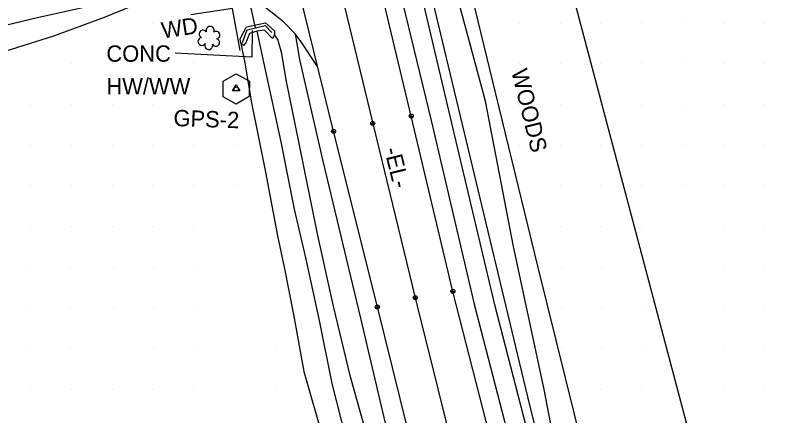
# Model space of a CAD drawing. Extents: x 1548934 to 1561348, y 809680 to 824075.
# Drawn here: x 1551496.2 to 1551685.3, y 811503.6 to 811602 of the extents above; entities that cross this region are included whole.
import ezdxf

# ---------------------------------------------------------------- set-up
doc = ezdxf.new("R2010")
doc.units = 0
for name, color, linetype in [('_CIVIL_CONSTRUCTION', 7, 'Continuous'), ('Default', 7, 'Continuous'), ('E_NCDOT_Horizontal_Alignment', 7, 'Continuous'), ('E_NCDOT_Vertical_Profile_Ground_Line', 7, 'Continuous'), ('Exist DTM QL2 LIDAR Elevation Point', 7, 'Continuous'), ('Exist Other Culture Fence Line Text', 7, 'Continuous'), ('Exist Structure Minor Culvert Topo', 7, 'Continuous'), ('Exist Structure Minor Head and End Wall Leader', 7, 'Continuous'), ('Exist Structure Minor Head and End Wall Text', 7, 'Continuous'), ('Exist Vegetation Shrub CELL', 7, 'Continuous'), ('Exist Vegetation Woods Line', 7, 'Continuous'), ('Exist Vegetation Woods Line Text', 7, 'Continuous'), ('P_NCDOT_Horizontal_Alignment', 7, 'Continuous'), ('P_NCDOT_Vertical_Profile_Grade_Minor_Road', 7, 'Continuous'), ('P_RDY_Dimension_Text', 7, 'Continuous'), ('P_RDY_Guardrail_Attenuator_Cell', 7, 'Continuous'), ('P_RDY_Paved_Shoulder', 7, 'Continuous'), ('PH Exist DTM Breakline', 7, 'Continuous'), ('Scratch_Level_6', 7, 'Continuous')]:
    doc.layers.add(name, color=color, linetype=linetype)

# ---------------------------------------------------------------- blocks, each defined once
blk = doc.blocks.new('SurveyPointCell')
at = {"layer": 'Default'}
for p, q in [((-0.5, 0), (0.5, 0)), ((0, -0.5), (0, 0.5))]:
    blk.add_line(p, q, dxfattribs=at)
blk.add_circle((0, 0), 0.5, dxfattribs=at)

msp = doc.modelspace()

# ---------------------------------------------------------------- linework, layer by layer
at = {"layer": '_CIVIL_CONSTRUCTION'}
msp.add_line((1551550.43, 811583.92), (1551550.43, 811583.92), dxfattribs=at)
msp.add_line((1551550.43, 811583.92), (1551550.43, 811583.92), dxfattribs=at)
msp.add_line((1551550.43, 811583.92), (1551550.43, 811583.92), dxfattribs=at)
msp.add_lwpolyline([(1551547.2, 811585.79), (1551550.45, 811587.6), (1551553.7, 811585.81), (1551553.65, 811582.09), (1551550.4, 811580.2), (1551547.2, 811582.01)], close=True, dxfattribs=at)
msp.add_lwpolyline([(1551547.2, 811585.79), (1551550.45, 811587.6), (1551553.7, 811585.81), (1551553.65, 811582.09), (1551550.4, 811580.2), (1551547.2, 811582.01)], close=True, dxfattribs=at)
msp.add_lwpolyline([(1551547.2, 811585.79), (1551550.45, 811587.6), (1551553.7, 811585.81), (1551553.65, 811582.09), (1551550.4, 811580.2), (1551547.2, 811582.01)], close=True, dxfattribs=at)
at = {"layer": 'E_NCDOT_Vertical_Profile_Ground_Line'}
for points in [[(1551637.28, 811403.02), (1551626.4, 811444.66), (1551615.07, 811489.43), (1551603.65, 811534.15), (1551593.42, 811577.24), (1551582.77, 811621.83), (1551571.37, 811669.46), (1551560.56, 811714.33), (1551550.2, 811757.15), (1551539.19, 811800.15), (1551527.36, 811844.37)], [(1551618.39, 811397.72), (1551607.45, 811440.85), (1551596.26, 811485.28), (1551585.1, 811530.33), (1551574.36, 811573.51), (1551563.53, 811617.58), (1551552.6, 811664.91), (1551541.75, 811709.22), (1551531.12, 811752.56), (1551520.63, 811794.97), (1551508.88, 811839.17)]]:
    msp.add_lwpolyline(points, dxfattribs=at)
at = {"layer": 'Exist DTM QL2 LIDAR Elevation Point'}
for p, q in [((1551529.98, 811600.06), (1551529.98, 811600.06)), ((1551539.98, 811600.06), (1551539.98, 811600.06)), ((1551619.99, 811600.06), (1551619.99, 811600.06)), ((1551629.99, 811600.06), (1551629.99, 811600.06)), ((1551639.99, 811600.06), (1551639.99, 811600.06)), ((1551649.99, 811600.06), (1551649.99, 811600.06)), ((1551659.99, 811600.06), (1551659.99, 811600.06)), ((1551669.99, 811600.06), (1551669.99, 811600.06)), ((1551679.99, 811600.06), (1551679.99, 811600.06)), ((1551509.98, 811590.06), (1551509.98, 811590.06)), ((1551519.98, 811590.06), (1551519.98, 811590.06)), ((1551529.98, 811590.06), (1551529.98, 811590.06)), ((1551539.98, 811590.06), (1551539.98, 811590.06)), ((1551619.99, 811590.06), (1551619.99, 811590.06)), ((1551629.99, 811590.06), (1551629.99, 811590.06)), ((1551639.99, 811590.06), (1551639.99, 811590.06)), ((1551649.99, 811590.06), (1551649.99, 811590.06)), ((1551659.99, 811590.06), (1551659.99, 811590.06)), ((1551669.99, 811590.06), (1551669.99, 811590.06)), ((1551679.99, 811590.06), (1551679.99, 811590.06)), ((1551499.98, 811580.06), (1551499.98, 811580.06)), ((1551509.98, 811580.06), (1551509.98, 811580.06)), ((1551519.98, 811580.06), (1551519.98, 811580.06)), ((1551529.98, 811580.06), (1551529.98, 811580.06)), ((1551539.98, 811580.06), (1551539.98, 811580.06)), ((1551619.99, 811580.06), (1551619.99, 811580.06)), ((1551629.99, 811580.06), (1551629.99, 811580.06)), ((1551639.99, 811580.06), (1551639.99, 811580.06)), ((1551649.99, 811580.06), (1551649.99, 811580.06)), ((1551659.99, 811580.06), (1551659.99, 811580.06)), ((1551669.99, 811580.06), (1551669.99, 811580.06)), ((1551679.99, 811580.06), (1551679.99, 811580.06)), ((1551499.98, 811570.06), (1551499.98, 811570.06)), ((1551509.98, 811570.06), (1551509.98, 811570.06)), ((1551519.98, 811570.06), (1551519.98, 811570.06)), ((1551529.98, 811570.06), (1551529.98, 811570.06)), ((1551539.98, 811570.06), (1551539.98, 811570.06)), ((1551549.98, 811570.06), (1551549.98, 811570.06)), ((1551619.99, 811570.06), (1551619.99, 811570.06)), ((1551629.99, 811570.06), (1551629.99, 811570.06)), ((1551639.99, 811570.06), (1551639.99, 811570.06)), ((1551649.99, 811570.06), (1551649.99, 811570.06)), ((1551659.99, 811570.06), (1551659.99, 811570.06)), ((1551669.99, 811570.06), (1551669.99, 811570.06)), ((1551679.99, 811570.06), (1551679.99, 811570.06)), ((1551499.98, 811560.06), (1551499.98, 811560.06)), ((1551509.98, 811560.06), (1551509.98, 811560.06)), ((1551519.98, 811560.06), (1551519.98, 811560.06)), ((1551529.98, 811560.06), (1551529.98, 811560.06)), ((1551539.98, 811560.06), (1551539.98, 811560.06)), ((1551549.98, 811560.06), (1551549.98, 811560.06)), ((1551629.99, 811560.06), (1551629.99, 811560.06)), ((1551639.99, 811560.06), (1551639.99, 811560.06)), ((1551649.99, 811560.06), (1551649.99, 811560.06)), ((1551659.99, 811560.06), (1551659.99, 811560.06)), ((1551669.99, 811560.06), (1551669.99, 811560.06)), ((1551679.99, 811560.06), (1551679.99, 811560.06)), ((1551499.98, 811550.05), (1551499.98, 811550.05)), ((1551509.98, 811550.05), (1551509.98, 811550.05)), ((1551519.98, 811550.05), (1551519.98, 811550.05)), ((1551529.98, 811550.05), (1551529.98, 811550.05)), ((1551539.98, 811550.05), (1551539.98, 811550.05)), ((1551549.98, 811550.05), (1551549.98, 811550.05)), ((1551629.99, 811550.05), (1551629.99, 811550.05)), ((1551639.99, 811550.05), (1551639.99, 811550.05)), ((1551649.99, 811550.05), (1551649.99, 811550.05)), ((1551659.99, 811550.05), (1551659.99, 811550.05)), ((1551669.99, 811550.05), (1551669.99, 811550.05)), ((1551679.99, 811550.05), (1551679.99, 811550.05)), ((1551499.98, 811540.05), (1551499.98, 811540.05)), ((1551509.98, 811540.05), (1551509.98, 811540.05)), ((1551519.98, 811540.05), (1551519.98, 811540.05)), ((1551529.98, 811540.05), (1551529.98, 811540.05)), ((1551539.98, 811540.05), (1551539.98, 811540.05)), ((1551549.98, 811540.05), (1551549.98, 811540.05)), ((1551629.99, 811540.05), (1551629.99, 811540.05)), ((1551639.99, 811540.05), (1551639.99, 811540.05)), ((1551649.99, 811540.05), (1551649.99, 811540.05)), ((1551659.99, 811540.05), (1551659.99, 811540.05)), ((1551669.99, 811540.05), (1551669.99, 811540.05)), ((1551679.99, 811540.05), (1551679.99, 811540.05)), ((1551499.98, 811530.05), (1551499.98, 811530.05)), ((1551509.98, 811530.05), (1551509.98, 811530.05)), ((1551519.98, 811530.05), (1551519.98, 811530.05)), ((1551529.98, 811530.05), (1551529.98, 811530.05)), ((1551539.98, 811530.05), (1551539.98, 811530.05)), ((1551549.98, 811530.05), (1551549.98, 811530.05)), ((1551629.99, 811530.05), (1551629.99, 811530.05)), ((1551639.99, 811530.05), (1551639.99, 811530.05)), ((1551649.99, 811530.05), (1551649.99, 811530.05)), ((1551659.99, 811530.05), (1551659.99, 811530.05)), ((1551669.99, 811530.05), (1551669.99, 811530.05)), ((1551679.99, 811530.05), (1551679.99, 811530.05)), ((1551499.98, 811520.05), (1551499.98, 811520.05)), ((1551509.98, 811520.05), (1551509.98, 811520.05)), ((1551529.98, 811520.05), (1551529.98, 811520.05)), ((1551539.98, 811520.05), (1551539.98, 811520.05)), ((1551549.98, 811520.05), (1551549.98, 811520.05)), ((1551559.98, 811520.05), (1551559.98, 811520.05)), ((1551629.99, 811520.05), (1551629.99, 811520.05)), ((1551639.99, 811520.05), (1551639.99, 811520.05)), ((1551649.99, 811520.05), (1551649.99, 811520.05)), ((1551659.99, 811520.05), (1551659.99, 811520.05)), ((1551669.99, 811520.05), (1551669.99, 811520.05)), ((1551679.99, 811520.05), (1551679.99, 811520.05)), ((1551499.98, 811510.05), (1551499.98, 811510.05)), ((1551509.98, 811510.05), (1551509.98, 811510.05)), ((1551519.98, 811510.05), (1551519.98, 811510.05)), ((1551529.98, 811510.05), (1551529.98, 811510.05)), ((1551539.98, 811510.05), (1551539.98, 811510.05)), ((1551549.98, 811510.05), (1551549.98, 811510.05)), ((1551559.98, 811510.05), (1551559.98, 811510.05)), ((1551639.99, 811510.05), (1551639.99, 811510.05)), ((1551649.99, 811510.05), (1551649.99, 811510.05)), ((1551659.99, 811510.05), (1551659.99, 811510.05)), ((1551669.99, 811510.05), (1551669.99, 811510.05)), ((1551679.99, 811510.05), (1551679.99, 811510.05))]:
    msp.add_line(p, q, dxfattribs=at)
at = {"layer": 'Exist Structure Minor Culvert Topo'}
msp.add_line((1551555.22, 811598.91), (1551544.95, 811644.87), dxfattribs=at)
at = {"layer": 'Exist Structure Minor Head and End Wall Leader'}
msp.add_line((1551554.38, 811598.24), (1551554.25, 811591.73), dxfattribs=at)
at = {"layer": 'Exist Structure Minor Head and End Wall Text'}
msp.add_line((1551554.25, 811591.73), (1551535.46, 811592.71), dxfattribs=at)
at = {"layer": 'Exist Vegetation Shrub CELL'}
msp.add_line((1551543.8, 811596.27), (1551543.8, 811596.27), dxfattribs=at)
for centre, radius, start, end in [((1551544.03, 811598.31), 0.99, 334.8391, 200.4717), ((1551542.32, 811597.4), 0.968, 35.8908, 245.4216), ((1551545.48, 811597.14), 0.929, 284.4567, 126.0861), ((1551542, 811595.57), 0.955, 95.1099, 327.9534), ((1551543.68, 811594.59), 0.984, 151.2797, 21.387), ((1551545.44, 811595.34), 0.937, 204.9913, 73.4601)]:
    msp.add_arc(centre, radius, start, end, dxfattribs=at)
at = {"layer": 'Exist Vegetation Woods Line'}
msp.add_lwpolyline([(1551571.72, 811842.18), (1551613.6, 811680.5), (1551674.88, 811449.43), (1551691.44, 811358.19), (1551695.57, 811334.77), (1551700.55, 811312.09), (1551699.58, 811308.43), (1551693.58, 811303.93), (1551678.43, 811304.73), (1551672.72, 811312.99), (1551668.24, 811325.43), (1551622.53, 811506.2), (1551580.25, 811682.82), (1551545.51, 811843.36)], dxfattribs=at)
at = {"layer": 'P_NCDOT_Horizontal_Alignment'}
msp.add_line((1551550.43, 811583.92), (1551550.43, 811583.92), dxfattribs=at)
msp.add_line((1551550.43, 811583.92), (1551550.43, 811583.92), dxfattribs=at)
msp.add_line((1551550.43, 811583.92), (1551550.43, 811583.92), dxfattribs=at)
msp.add_lwpolyline([(1551549.57, 811583.42), (1551550.43, 811584.92), (1551551.3, 811583.42)], close=True, dxfattribs=at)
msp.add_lwpolyline([(1551549.57, 811583.42), (1551550.43, 811584.92), (1551551.3, 811583.42)], close=True, dxfattribs=at)
msp.add_lwpolyline([(1551549.57, 811583.42), (1551550.43, 811584.92), (1551551.3, 811583.42)], close=True, dxfattribs=at)
msp.add_circle((1551550.43, 811583.92), 0.5, dxfattribs=at)
msp.add_circle((1551550.43, 811583.92), 0.5, dxfattribs=at)
msp.add_circle((1551550.43, 811583.92), 0.5, dxfattribs=at)
at = {"layer": 'P_NCDOT_Vertical_Profile_Grade_Minor_Road'}
msp.add_lwpolyline([(1551518.46, 811841.68), (1551529.96, 811797.42), (1551540.4, 811755.31), (1551551.09, 811711.95), (1551562.08, 811668.09), (1551573.17, 811620.17), (1551583.96, 811575.43), (1551594.4, 811532.6), (1551605.57, 811487.55), (1551616.79, 811443.3), (1551627.43, 811400.69)], dxfattribs=at)
at = {"layer": 'P_RDY_Dimension_Text'}
for points in [[(1551587.8, 811693.01), (1551592.22, 811675.36), (1551603.34, 811627.3), (1551614.09, 811582.73), (1551624.5, 811540), (1551635.64, 811495.08), (1551646.85, 811450.87), (1551657.51, 811408.2)], [(1551551.39, 811593.34), (1551549.5, 811603.72), (1551539.28, 811602.16)]]:
    msp.add_lwpolyline(points, dxfattribs=at)
at = {"layer": 'P_RDY_Guardrail_Attenuator_Cell'}
msp.add_lwpolyline([(1551552.02, 811595.34), (1551553.17, 811598.4), (1551557.57, 811599.48), (1551559.15, 811597.81)], dxfattribs=at)
at = {"layer": 'P_RDY_Paved_Shoulder'}
for points in [[(1551519.39, 811605.3), (1551501.99, 811601.47), (1551487.86, 811598.11)], [(1551570.44, 811589.44), (1551566.2, 811595.74), (1551564.93, 811597.45), (1551562.14, 811600.35), (1551560.1, 811601.98), (1551555.9, 811605.25)]]:
    msp.add_lwpolyline(points, dxfattribs=at)
at = {"layer": 'PH Exist DTM Breakline'}
for points in [[(1551669.67, 811303.01), (1551663.46, 811331.84), (1551653.59, 811372.99), (1551648.84, 811392.4), (1551636.09, 811443.6), (1551626.8, 811481.01), (1551614.05, 811530.5), (1551603.71, 811574.11), (1551596.24, 811605.78), (1551582.53, 811665.38), (1551576.53, 811692.42), (1551569, 811727.51), (1551561.82, 811755.9), (1551554.82, 811782.6), (1551545.34, 811820.46), (1551541.31, 811835.52)], [(1551534.96, 811833.74), (1551549.41, 811779.1), (1551560.58, 811733.74), (1551572.57, 811684.16), (1551581.33, 811646.33), (1551598.34, 811576.19), (1551608.87, 811531.03), (1551621.47, 811482.36), (1551627.81, 811455.82), (1551633.18, 811432.34), (1551647.15, 811378.38), (1551657.12, 811338.6), (1551669.09, 811290.08), (1551679.12, 811250.32), (1551691.58, 811200.98), (1551703.42, 811153.47), (1551715.6, 811112.46)], [(1551629.75, 811490.89), (1551625.97, 811510.44), (1551618.5, 811545.18), (1551611.68, 811580.87), (1551604.06, 811609.22), (1551598.21, 811634.59)], [(1551533.88, 811607.99), (1551518, 811601.43), (1551505.58, 811596.91), (1551495.19, 811593.59), (1551479.51, 811588.92), (1551464.97, 811584.58), (1551454.34, 811581.38), (1551442.17, 811577.73), (1551429.7, 811573.12)], [(1551583.68, 811494.7), (1551578.54, 811513.17), (1551574.36, 811530.51), (1551570.51, 811547.88), (1551565.91, 811570.48), (1551562.74, 811586.12), (1551561.61, 811592.62), (1551560.7, 811596.04), (1551559.81, 811597.21), (1551559.33, 811596.34), (1551557.35, 811598.39), (1551555.63, 811598.08), (1551553.71, 811597.55), (1551552.83, 811595.21), (1551552.21, 811594.57), (1551551.59, 811595.13), (1551551.41, 811596.26), (1551553.01, 811599.14), (1551557.65, 811600.18), (1551559.88, 811598.21), (1551559.81, 811597.21)], [(1551577.51, 811497.69), (1551574.04, 811511.54), (1551570.93, 811527), (1551567.66, 811542.11), (1551564.76, 811554.33), (1551561.47, 811570.91), (1551557.66, 811588.58), (1551555.63, 811598.08)], [(1551564.93, 811597.45), (1551565.95, 811591.13), (1551571.72, 811566.17), (1551580.97, 811527.55), (1551588.92, 811493.71), (1551596.94, 811459.96), (1551610.36, 811408), (1551619.28, 811375.03), (1551624.14, 811357.87), (1551624.42, 811355), (1551626.26, 811350.74)], [(1551551.59, 811595.13), (1551552.55, 811590.33), (1551554.14, 811580.89), (1551557.65, 811563.47), (1551560.61, 811547.82), (1551562.22, 811540.15), (1551564.51, 811528.49), (1551567.05, 811514.46), (1551571.86, 811497.56)]]:
    msp.add_lwpolyline(points, dxfattribs=at)

# ---------------------------------------------------------------- block references
at = {"layer": 'Default'}
for p in [(1551593.42, 811577.24), (1551583.96, 811575.43), (1551574.36, 811573.51), (1551603.65, 811534.15), (1551594.4, 811532.6), (1551585.1, 811530.33)]:
    msp.add_blockref('SurveyPointCell', p, dxfattribs=at)

# ---------------------------------------------------------------- texts
at = {"layer": 'E_NCDOT_Horizontal_Alignment'}
msp.add_text('-EL-', height=4.02, rotation=283.7191, dxfattribs=at).set_placement((1551586.76, 811569.08))
at = {"layer": 'Exist Other Culture Fence Line Text'}
msp.add_text('WD', height=4.02, rotation=8.6645, dxfattribs=at).set_placement((1551532.41, 811596.28))
at = {"layer": 'Exist Structure Minor Head and End Wall Text'}
for s, p in [('CONC', (1551518.57, 811590.59)), ('HW/WW', (1551518.57, 811582.55))]:
    msp.add_text(s, height=4.02, dxfattribs=at).set_placement(p)
at = {"layer": 'Exist Vegetation Woods Line Text'}
msp.add_text('WOODS', height=4.02, rotation=283.9521, dxfattribs=at).set_placement((1551617.95, 811588.28))
at = {"layer": 'Scratch_Level_6'}
msp.add_text('GPS-2', height=4.02, rotation=358, dxfattribs=at).set_placement((1551534.99, 811574.8))

doc.saveas('drawing.dxf')
